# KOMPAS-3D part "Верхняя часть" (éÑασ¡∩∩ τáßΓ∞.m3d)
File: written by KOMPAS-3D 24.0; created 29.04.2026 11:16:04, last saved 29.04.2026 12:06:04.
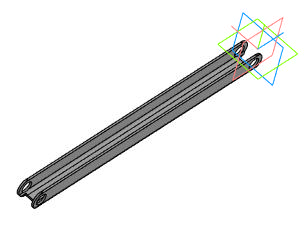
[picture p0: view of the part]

Document properties: Автор: USG_411; Полное имя файла: C:\Users\USG_411\Desktop\ИА-2904_411-12\Верхняя часть.m3d

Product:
- Part/product: Верхняя часть
    Масса: 0.236991

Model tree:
1. Эскиз:1
2. Элемент выдавливания:1
     Расстояние 2 = 298
3. Эскиз:2  (with: Грань.Элемент выдавливания:1)
4. Элемент выдавливания:2
     Расстояние 2 = 20
5. Эскиз:3  (with: Грань.Элемент выдавливания:1, Ребро.Элемент выдавливания:1, Ребро.Элемент выдавливания:2)
6. Элемент выдавливания:3
     Расстояние 1 = 10; Расстояние 2 = 10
